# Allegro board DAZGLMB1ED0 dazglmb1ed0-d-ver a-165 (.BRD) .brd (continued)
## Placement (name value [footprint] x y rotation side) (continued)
C94914  10u/6.3V_4  [C0402_2]  236.34 74.79 0 bottom
C94915  10u/6.3V_4  [C0402_2]  269.72 61.94 0 bottom
C94916  10u/6.3V_4  [C0402_2]  227.34 74.95 270 bottom
C94918  10u/6.3V_4  [C0402_2]  221.76 66.49 180 bottom
C94919  0.022u/50V_4  [C0402]  239.35 69.61 0 bottom
C94921  *10u/6.3V_4  [C0402_2]  45.61 49.88 90 top
C94922  10u/6.3V_4  [C0402_2]  24.4 30.22 180 top
C94923  0.1u/10V_2  [C0201]  24.68 29.1 0 top
C94924  100p/50V_4  [C0402]  21.36 33.11 270 bottom
C94925  2.2u/10V_6  [C0603]  24.25 35.6 270 top
C94926  2.2u/10V_4  [C0402]  25.42 27.14 180 top
C94927  10u/6.3V_4  [C0402_2]  27.27 25.19 270 top
C94928  0.1u/10V_2  [C0201]  27.33 26.84 0 top
C94929  2.2u/10V_6  [C0603]  25.72 35.65 270 top
C94930  10u/6.3V_4  [C0402_2]  25.8 26 180 top
C94931  10u/6.3V_4  [C0402_2]  25.27 34.94 0 bottom
C94932  0.1u/10V_2  [C0201]  26.56 34.84 270 bottom
C94933  10u/6.3V_4  [C0402_2]  27.86 34.76 180 bottom
C94934  0.1u/10V_2  [C0201]  29.05 25.62 90 top
C94937  10u/6.3V_4  [C0402_2]  29.74 34.48 90 bottom
C94938  10u/6.3V_4  [C0402_2]  34.08 24.78 0 top
C94939  0.1u/10V_2  [C0201]  30.25 24.73 0 top
C94940  10u/6.3V_4  [C0402_2]  30.53 28.46 90 bottom
C94942  100p/50V_4  [C0402]  16.4 16.73 270 top
C94943  100p/50V_4  [C0402]  16.2 9.74 90 top
C94945  10u/6.3V_4  [C0402_2]  29.1 24.6 270 bottom
C94946  0.1u/10V_2  [C0201]  33.83 27.52 180 top
C94947  *22p/50V_4  [C0402]  32.35 33.7 90 bottom
C94951  *1000p/50V_4  [C0402]  15.67 31.56 90 bottom
C94952  100p/50V_4  [C0402]  20.98 23.66 270 top
C94953  100p/50V_4  [C0402]  23.24 27.02 270 top
C94956  *0.1u/10V_2  [C0201]  21.74 14.85 315 top
C94958  1000p/50V_4  [C0402]  21.48 12.41 90 top
C94959  1000p/50V_4  [C0402]  22.63 12.41 90 top
C94960  1000p/50V_4  [C0402]  23.77 12.41 90 top
C94961  1000p/50V_4  [C0402]  24.91 12.41 90 top
C94962  0.1u/10V_2  [C0201]  20.47 31.08 90 top
C94963  10u/6.3V_4  [C0402_2]  22.63 31.84 90 top
C94964  0.1u/10V_2  [C0201]  22.88 36.24 180 top
C94965  10u/6.3V_4  [C0402_2]  22.68 34.74 270 top
C94966  *1u/6.3V_2  [C0201]  34.56 29.07 270 top
C94967  *10p/50V_4  [C0402]  36.85 33.75 180 top
C94968  10p/50V_4  [C0402]  36.88 35.09 180 top
C94969  0.1u/10V_2  [C0201]  347.75 71.34 0 bottom
C94970  1u/6.3V_2  [C0201]  347.75 70.58 180 bottom
C94971  1000p/50V_4  [C0402]  343.68 67.1 270 top
C94972  0.1u/10V_2  [C0201]  342.82 67.3 270 top
C94973  10u/6.3V_4  [C0402_2]  344.83 67.1 270 top
C94974  0.1u/10V_2  [C0201]  347.72 72.86 180 bottom
C94975  0.1u/10V_2  [C0201]  348.36 75.4 270 top
C94976  0.1u/10V_2  [C0201]  349.12 75.4 270 top
C94977  1u/6.3V_2  [C0201]  350.67 68.75 270 bottom
C94978  0.1u/10V_2  [C0201]  349.88 68.75 90 bottom
C94979  10u/6.3V_4  [C0402_2]  346.72 65.45 180 top
C94980  0.1u/10V_2  [C0201]  351.43 68.75 90 bottom
C94981  0.1u/10V_2  [C0201]  351.78 74.08 90 bottom
C94982  10u/6.3V_4  [C0402_2]  346.86 66.67 180 top
C94983  1u/6.3V_2  [C0201]  347.49 67.76 270 top
C94984  1u/6.3V_2  [C0201]  352.22 68.75 270 bottom
C94985  0.1u/10V_2  [C0201]  346.73 67.76 90 top
C94986  *1000p/50V_4  [C0402]  346.86 67.02 180 bottom
C94987  0.1u/10V_2  [C0201]  353.08 70.58 180 bottom
C94988  0.1u/10V_2  [C0201]  353.08 72.86 0 bottom
C94989  0.1u/10V_2  [C0201]  353.08 72.1 0 bottom
C94990  1u/6.3V_2  [C0201]  353.08 71.34 0 bottom
C94991  18p/50V_4  [C0402]  352.62 66.62 0 top
C94992  0.01u/50V_4  [C0402]  358.8 67.02 90 bottom
C94993  18p/50V_4  [C0402]  350.9 66.62 180 top
C95000  1000p/3KV_1808  [CC1808]  366.42 80.23 180 top
C95002  4.7u/6.3V_4  [C0402_2]  189.5 110.58 0 bottom
C95003  1u/6.3V_2  [C0201]  156.87 122.14 270 bottom
C95004  1u/6.3V_2  [C0201]  188.23 113.12 180 bottom
C95005  1u/6.3V_2  [C0201]  166.85 122.01 270 bottom
C95006  0.22u/6.3V_2  [C0201]  156.43 108.55 270 bottom
C95007  22u/6.3V_6  [C0603]  138.83 126.84 270 bottom
C95008  10u/6.3V_4  [C0402_2]  161.49 124.35 0 bottom
C95009  10u/6.3V_4  [C0402_2]  161.49 125.54 0 bottom
C95010  0.22u/6.3V_2  [C0201]  158.59 107.15 270 bottom
C95011  4.7u/6.3V_4  [C0402_2]  137.43 122.65 270 bottom
C95012  22u/6.3V_6  [C0603]  190.39 109.19 180 bottom
C95013  10u/6.3V_4  [C0402_2]  188.87 111.85 0 bottom
C95014  10u/6.3V_4  [C0402_2]  168.17 122.39 90 bottom
C95015  1u/6.3V_2  [C0201]  153.01 122.01 270 bottom
C95016  4.7u/6.3V_4  [C0402_2]  154.45 102.58 90 bottom
C95017  0.22u/6.3V_2  [C0201]  154.78 108.42 270 bottom
C95018  0.22u/6.3V_2  [C0201]  155.54 108.42 270 bottom
C95019  0.22u/6.3V_2  [C0201]  157.2 108.55 270 bottom
C95020  0.22u/6.3V_2  [C0201]  157.83 107.15 270 bottom
C95021  4.7u/6.3V_4  [C0402_2]  140.23 126.71 90 bottom
C95022  1u/6.3V_2  [C0201]  151.91 127.98 180 bottom
C95023  1u/6.3V_2  [C0201]  151.91 125.7 180 bottom
C95024  1u/6.3V_2  [C0201]  161.44 121.86 180 bottom
C95025  1u/6.3V_2  [C0201]  164.72 122.01 270 bottom
C95026  0.22u/6.3V_2  [C0201]  159.1 106.14 90 bottom
C95027  0.22u/6.3V_2  [C0201]  159.86 106.14 90 bottom
C95028  0.22u/6.3V_2  [C0201]  160.5 109.44 90 bottom
C95029  0.22u/6.3V_2  [C0201]  161.26 109.44 90 bottom
C95030  0.22u/6.3V_2  [C0201]  161.39 107.79 90 bottom
C95031  0.22u/6.3V_2  [C0201]  162.15 107.79 90 bottom
C95032  0.22u/6.3V_2  [C0201]  162.91 108.04 90 bottom
C95033  0.1u/10V_2  [C0201]  163.37 122.95 90 bottom
C95034  0.22u/6.3V_2  [C0201]  163.67 108.04 90 bottom
C95035  0.22u/6.3V_2  [C0201]  164.18 109.95 90 bottom
C95036  0.22u/6.3V_2  [C0201]  164.94 109.95 90 bottom
C95037  0.22u/6.3V_2  [C0201]  164.94 108.17 90 bottom
C95038  0.22u/6.3V_2  [C0201]  165.7 108.17 90 bottom
C95039  0.22u/6.3V_2  [C0201]  166.09 107.15 90 bottom
C95040  0.22u/6.3V_2  [C0201]  166.85 107.15 90 bottom
C95041  0.22u/6.3V_2  [C0201]  167.13 108.93 90 bottom
C95042  0.22u/6.3V_2  [C0201]  167.89 108.93 90 bottom
C95043  0.22u/6.3V_2  [C0201]  168.24 107.53 90 bottom
C95044  0.22u/6.3V_2  [C0201]  169.01 107.53 90 bottom
C95045  0.22u/6.3V_2  [C0201]  169.74 107.53 90 bottom
C95046  0.22u/6.3V_2  [C0201]  170.5 107.53 90 bottom
C95047  0.1u/10V_2  [C0201]  170.91 132.2 180 bottom
C95048  22u/6.3V_6  [C0603]  166.64 102.71 0 top
C95049  0.22u/6.3V_2  [C0201]  170.53 109.31 90 bottom
C95050  0.22u/6.3V_2  [C0201]  171.29 109.31 90 bottom
C95051  0.22u/6.3V_2  [C0201]  171.67 107.53 90 bottom
C95052  0.22u/6.3V_2  [C0201]  172.44 107.53 90 bottom
C95053  0.1u/10V_2  [C0201]  162.55 141.22 90 bottom
C95054  0.1u/10V_2  [C0201]  170.94 127.35 0 bottom
C95055  0.22u/6.3V_2  [C0201]  172.82 106.14 90 bottom
C95056  0.22u/6.3V_2  [C0201]  173.58 106.14 90 bottom
C95057  0.1u/10V_2  [C0201]  134.77 115.03 180 top
C95058  0.1u/10V_2  [C0201]  153.82 141.19 90 bottom
C95059  0.1u/10V_2  [C0201]  154.58 141.19 270 bottom
C95060  0.1u/10V_2  [C0201]  151.3 137.05 0 bottom
C95065  0.1u/10V_2  [C0201]  151.59 122.01 270 bottom
C95066  4.7u/6.3V_4  [C0402_2]  154.45 100.42 90 bottom
C95067  4.7u/6.3V_4  [C0402_2]  155.85 102.58 270 bottom
C95068  0.1u/10V_2  [C0201]  154.93 122.14 270 bottom
C95069  1u/6.3V_2  [C0201]  165.43 122.01 90 bottom
C95070  0.1u/10V_2  [C0201]  159.66 121.96 270 bottom
C95071  4.7u/6.3V_4  [C0402_2]  158.26 122.52 270 bottom
C95072  4.7u/6.3V_4  [C0402_2]  157.25 100.42 90 bottom
C95073  1u/6.3V_2  [C0201]  155.64 122.17 90 bottom
C95074  4.7u/6.3V_4  [C0402_2]  155.85 100.42 90 bottom
C95075  4.7u/6.3V_4  [C0402_2]  153.97 122.39 270 bottom
C95076  0.1u/10V_2  [C0201]  169.64 122.01 270 bottom
C95077  1u/6.3V_2  [C0201]  166.14 122.01 90 bottom
C95078  0.1u/10V_2  [C0201]  124.99 104.61 180 top
C95079  *220p/50V_4  [C0402]  133.55 117.44 270 top
C95080  *220p/50V_4  [C0402]  130.2 116.17 90 bottom
C95081  *220p/50V_4  [C0402]  142.44 101.41 180 top
C95082  1u/6.3V_2  [C0201]  170.94 130.45 0 bottom
C95083  1u/6.3V_2  [C0201]  170.94 131.46 0 bottom
C95084  1u/6.3V_2  [C0201]  156.1 141.19 90 bottom
C95085  10u/6.3V_4  [C0402_2]  118.64 154.4 180 bottom
C95086  1u/6.3V_2  [C0201]  170.94 134.18 0 bottom
C95087  10u/6.3V_4  [C0402_2]  203.22 145.04 180 bottom
C95088  1u/6.3V_2  [C0201]  151.4 130.01 180 bottom
C95089  10u/6.3V_4  [C0402_2]  201.49 145.04 0 bottom
C95090  1u/6.3V_2  [C0201]  171.22 139.67 0 bottom
C95091  10u/6.3V_4  [C0402_2]  163.88 140.89 90 bottom
C95092  1u/6.3V_2  [C0201]  155.34 141.19 90 bottom
C95093  10u/6.3V_4  [C0402_2]  168.55 156.56 270 bottom
C95094  1u/6.3V_2  [C0201]  170.94 134.94 0 bottom
C95095  10u/6.3V_4  [C0402_2]  152.85 141.57 90 bottom
C95096  1u/6.3V_2  [C0201]  170.94 135.75 0 bottom
C95097  10u/6.3V_4  [C0402_2]  181 163.16 0 bottom
C95098  1u/6.3V_2  [C0201]  165.02 141.24 90 bottom
C95099  *10u/6.3V_4  [C0402_2]  170.56 126.38 0 bottom
C95100  1u/6.3V_2  [C0201]  151.23 135.47 180 bottom
C95101  47u/6.3V_6  [C0603]  151.33 140.48 90 bottom
C95102  1u/6.3V_2  [C0201]  151.66 133.34 180 bottom
C95103  22u/6.3V_6  [C0603]  184.14 146.19 180 bottom
C95104  1u/6.3V_2  [C0201]  170.96 133.47 0 bottom
C95105  22u/6.3V_6  [C0603]  118.26 171.16 0 top
C95106  1u/6.3V_2  [C0201]  170.94 128.08 0 bottom
C95107  22u/6.3V_6  [C0603]  182.75 132.78 90 bottom
C95108  1u/6.3V_2  [C0201]  151.66 134.05 180 bottom
C95109  22u/6.3V_6  [C0603]  139.59 138.52 180 bottom
C95110  1u/6.3V_2  [C0201]  165.73 141.24 90 bottom
C95111  22u/6.3V_6  [C0603]  174.77 156.68 270 bottom
C95112  1u/6.3V_2  [C0201]  151.28 136.26 180 bottom
C95113  22u/6.3V_6  [C0603]  173.12 156.68 270 bottom
C95114  1u/6.3V_2  [C0201]  156.87 141.19 90 bottom
C95115  22u/6.3V_6  [C0603]  118.26 169.64 0 top
C95116  1u/6.3V_2  [C0201]  151.3 138.57 180 bottom
C95117  22u/6.3V_6  [C0603]  138.73 148.58 180 bottom
C95118  1u/6.3V_2  [C0201]  151.3 137.86 180 bottom
C95119  *47u/6.3V_6  [C0603]  139.59 136.11 180 bottom
C95120  1u/6.3V_2  [C0201]  170.94 136.52 0 bottom
C95121  1u/6.3V_2  [C0201]  157.63 141.19 90 bottom
C95122  1u/6.3V_2  [C0201]  151.4 130.78 180 bottom
C95123  1u/6.3V_2  [C0201]  170.94 128.82 0 bottom
C95124  10u/6.3V_4  [C0402_2]  158.87 141.55 90 bottom
C95125  10u/6.3V_4  [C0402_2]  168.22 141.27 0 bottom
C95126  10u/6.3V_4  [C0402_2]  170.07 141.22 0 bottom
C95127  10u/6.3V_4  [C0402_2]  169.95 156.56 270 bottom
C95128  10u/6.3V_4  [C0402_2]  202.59 126.46 0 bottom
C95129  *47u/6.3V_6  [C0603]  138.73 145.66 180 bottom
C95130  *47u/6.3V_6  [C0603]  184.14 144.54 180 bottom
C95131  0.1u/10V_2  [C0201]  150.72 121.89 180 bottom
C95132  0.1u/10V_2  [C0201]  150.72 122.6 180 bottom
C95133  4.7u/6.3V_4  [C0402_2]  103.53 66.77 180 bottom
C95134  1u/6.3V_2  [C0201]  134.89 122.27 90 bottom
C95135  1u/6.3V_2  [C0201]  150.62 127.91 270 bottom
C95136  1u/6.3V_2  [C0201]  161.44 123.38 180 bottom
C95137  1u/6.3V_2  [C0201]  161.44 122.62 180 bottom
C95138  4.7u/6.3V_4  [C0402_2]  151.86 124.43 90 bottom
C95139  4.7u/6.3V_4  [C0402_2]  139.97 122.65 90 bottom
C95140  4.7u/6.3V_4  [C0402_2]  138.7 122.65 90 bottom
C95141  0.1u/10V_2  [C0201]  150.77 125.44 180 bottom
C95142  0.1u/10V_2  [C0201]  150.77 124.02 180 bottom
C95143  0.1u/10V_2  [C0201]  150.77 126.15 180 bottom
C95144  0.1u/10V_2  [C0201]  151.91 127.22 180 bottom
C95145  0.1u/10V_2  [C0201]  150.77 123.31 180 bottom
C95146  0.1u/10V_2  [C0201]  150.77 124.73 180 bottom
C95147  0.1u/10V_2  [C0201]  151.91 126.46 180 bottom
C95148  0.1u/10V_2  [C0201]  125.32 120.39 0 top
C95149  *0.1u/10V_2  [C0201]  113.81 120.11 0 bottom
C95150  *60@0.22u/6.3V_2  [C0201]  121.31 120.11 0 bottom
C95151  0.1u/10V_2  [C0201]  152.3 122.01 270 bottom
C95152  0.1u/10V_2  [C0201]  152.29 111.98 0 bottom
C95153  4.7u/6.3V_4  [C0402_2]  151.53 110.46 0 bottom
C95154  0.1u/10V_2  [C0201]  153.82 112.74 0 bottom
C95155  0.1u/10V_2  [C0201]  170.94 137.25 180 bottom
C95156  0.1u/10V_2  [C0201]  151.28 131.92 270 bottom
C95157  22u/6.3V_6  [C0603]  153.06 107.79 0 bottom
C95158  *0.1u/10V_2  [C0201]  121.81 114.27 0 bottom
C95159  10p/50V_4  [C0402]  148.1 107.79 180 top
C95160  10p/50V_4  [C0402]  146.32 107.79 0 top
C95161  22u/6.3V_6  [C0603]  178.68 107.56 0 top
C95162  22u/6.3V_6  [C0603]  186.13 113.63 270 top
C95163  47u/6.3V_6  [C0603]  157.02 132.07 270 bottom
C95164  47u/6.3V_6  [C0603]  155.6 132.05 270 bottom
C95165  47u/6.3V_6  [C0603]  165.42 128.54 270 bottom
C95166  47u/6.3V_6  [C0603]  164 128.54 270 bottom
C95167  47u/6.3V_6  [C0603]  164.49 131.36 90 bottom
C95168  *22u/6.3V_6  [C0603]  182.39 122.14 270 bottom
C95169  1u/6.3V_2  [C0201]  158.29 129.84 270 bottom
C95170  1u/6.3V_2  [C0201]  158.31 138.22 270 bottom
C95171  10u/6.3V_4  [C0402_2]  169.44 124.83 270 bottom
C95172  1u/6.3V_2  [C0201]  156.03 140.33 180 bottom
C95173  1u/6.3V_2  [C0201]  162.96 131.49 180 bottom
C95174  47u/6.3V_6  [C0603]  161.13 133.16 180 bottom
C95175  47u/6.3V_6  [C0603]  156.28 134.46 180 bottom
C95176  10u/6.3V_4  [C0402_2]  169.46 134.43 90 bottom
C95177  1u/6.3V_2  [C0201]  158.31 125.06 90 bottom
C95178  10u/6.3V_4  [C0402_2]  168.14 124.76 270 bottom
C95179  10u/6.3V_4  [C0402_2]  166.69 135.25 90 bottom
C95180  1u/6.3V_2  [C0201]  166.75 124.98 90 bottom
C95181  10u/6.3V_4  [C0402_2]  160.37 141.29 0 bottom
C95182  1u/6.3V_2  [C0201]  154.1 131.56 270 bottom
C95183  10u/6.3V_4  [C0402_2]  165.27 139.51 90 bottom
C95184  1u/6.3V_2  [C0201]  159.66 122.95 90 bottom
C95185  10u/6.3V_4  [C0402_2]  169.57 128.95 90 bottom
C95186  1u/6.3V_2  [C0201]  154.12 136.16 90 bottom
C95187  1u/6.3V_2  [C0201]  154.12 128.77 90 bottom
C95188  10u/6.3V_4  [C0402_2]  165.27 135.25 90 bottom
C95189  1u/6.3V_2  [C0201]  168.09 138.19 270 bottom
C95190  1u/6.3V_2  [C0201]  168.12 136.62 270 bottom
C95191  10u/6.3V_4  [C0402_2]  171.5 124.25 270 bottom
C95192  1u/6.3V_2  [C0201]  156.92 136.26 270 bottom
C95193  1u/6.3V_2  [C0201]  169.51 123.46 90 bottom
C95194  10u/6.3V_4  [C0402_2]  166.69 140.38 270 bottom
C95195  1u/6.3V_2  [C0201]  156.89 139.54 270 bottom
C95196  1u/6.3V_2  [C0201]  154.1 134.48 90 bottom
C95197  10u/6.3V_4  [C0402_2]  171.24 122.17 0 bottom
C95198  1u/6.3V_2  [C0201]  168.04 128.16 270 bottom
C95199  1u/6.3V_2  [C0201]  169.54 131.33 90 bottom
C95200  1u/6.3V_2  [C0201]  153.08 131.39 270 bottom
C95201  1u/6.3V_2  [C0201]  162.35 126.58 180 bottom
C95202  47u/6.3V_6  [C0603]  161.11 135.98 0 bottom
C95203  1u/6.3V_2  [C0201]  154.15 138.85 90 bottom
C95204  1u/6.3V_2  [C0201]  169.54 137.23 90 bottom
C95205  22u/6.3V_6  [C0603]  183.92 122.14 270 bottom
C95206  1u/6.3V_2  [C0201]  154.12 126.76 270 bottom
C95207  1u/6.3V_2  [C0201]  153.92 123.64 180 bottom
C95208  22u/6.3V_6  [C0603]  178.71 105.88 0 top
C95209  1u/6.3V_2  [C0201]  158.31 124.04 270 bottom
C95210  1u/6.3V_2  [C0201]  168.04 139.54 270 bottom
C95211  47u/6.3V_6  [C0603]  161.11 127.96 180 bottom
C95212  1u/6.3V_2  [C0201]  158.9 136.52 270 bottom
C95213  1u/6.3V_2  [C0201]  152.04 129 90 bottom
C95214  1u/6.3V_2  [C0201]  152.14 135.81 90 bottom
C95215  1u/6.3V_2  [C0201]  169.54 136.24 270 bottom
C95216  1u/6.3V_2  [C0201]  158.29 128.85 90 bottom
C95217  1u/6.3V_2  [C0201]  154.17 140.12 90 bottom
C95218  1u/6.3V_2  [C0201]  163.88 135.27 270 bottom
C95219  1u/6.3V_2  [C0201]  156.89 128.85 90 bottom
C95220  1u/6.3V_2  [C0201]  155.52 126.79 270 bottom
C95221  1u/6.3V_2  [C0201]  154.1 125.01 90 bottom
C95222  10u/6.3V_4  [C0402_2]  160.95 131.66 180 bottom
C95223  10u/6.3V_4  [C0402_2]  168.07 134.54 270 bottom
C95224  1u/6.3V_2  [C0201]  156.89 129.84 270 bottom
C95225  10u/6.3V_4  [C0402_2]  168.14 131 270 bottom
C95226  47u/6.3V_6  [C0603]  165.91 131.36 90 bottom
C95227  1u/6.3V_2  [C0201]  165.32 133.6 270 bottom
C95228  10u/6.3V_4  [C0402_2]  154.15 132.99 270 bottom
C95229  47u/6.3V_6  [C0603]  170.23 138.45 180 bottom
C95230  1u/6.3V_2  [C0201]  163.49 126.46 0 bottom
C95231  47u/6.3V_6  [C0603]  161.11 137.41 0 bottom
C95232  1u/6.3V_2  [C0201]  160.68 126.51 180 bottom
C95233  1u/6.3V_2  [C0201]  166.64 133.6 270 bottom
C95234  1u/6.3V_2  [C0201]  156.84 126.81 270 bottom
C95235  47u/6.3V_6  [C0603]  161.11 139.84 180 bottom
C95236  1u/6.3V_2  [C0201]  163.93 137.96 270 bottom
C95237  47u/6.3V_6  [C0603]  161.11 129.38 0 bottom
C95238  330u/2V_7343H1.9  [CC7343]  197.25 101.13 0 top
C95239  1u/6.3V_2  [C0201]  169.9 132.88 0 bottom
C95240  1u/6.3V_2  [C0201]  166.67 137.86 270 bottom
C95241  1u/6.3V_2  [C0201]  154.12 130.52 90 bottom
C95242  330u/2V_7343H1.9  [CC7343]  196.73 96.37 0 top
C95243  1u/6.3V_2  [C0201]  168.07 129.58 270 bottom
C95244  1u/6.3V_2  [C0201]  160.27 124.68 90 bottom
C95245  1u/6.3V_2  [C0201]  163.9 133.57 270 bottom
C95246  1u/6.3V_2  [C0201]  155.54 128.85 90 bottom
C95247  1u/6.3V_2  [C0201]  156.84 138.01 270 bottom
C95248  1u/6.3V_2  [C0201]  165.25 126.1 90 bottom
C95249  1u/6.3V_2  [C0201]  155.57 125.09 90 bottom
C95250  1u/6.3V_2  [C0201]  158.41 140.12 90 bottom
C95251  1u/6.3V_2  [C0201]  152.01 131.92 270 bottom
C95252  1u/6.3V_2  [C0201]  155.54 129.84 270 bottom
C95253  1u/6.3V_2  [C0201]  165.27 137.96 270 bottom
C95254  1u/6.3V_2  [C0201]  156.89 124.02 270 bottom
C95255  1u/6.3V_2  [C0201]  156.89 125.09 90 bottom
C95256  1u/6.3V_2  [C0201]  158.29 126.79 270 bottom
C95257  1u/6.3V_2  [C0201]  168.04 127.17 90 bottom
C95258  1u/6.3V_2  [C0201]  163.9 139.46 270 bottom
C95259  1u/6.3V_2  [C0201]  155.57 124.07 270 bottom
C95260  1u/6.3V_2  [C0201]  168.09 133.16 90 bottom
C95261  1u/6.3V_2  [C0201]  155.62 136.29 270 bottom
C95496  1u/6.3V_2  [C0201]  23.18 63.42 270 top
C95498  0.1u/10V_2  [C0201]  16.96 45.61 180 bottom
C95499  22u/6.3V_4  [C0402]  17.04 44.52 0 bottom
C95500  22u/6.3V_4  [C0402_2]  17.04 43.25 180 bottom
C95501  0.1u/10V_2  [C0201]  16.89 40.4 90 bottom
C95502  22u/6.3V_4  [C0402]  18.44 64.1 270 top
C95503  0.1u/10V_2  [C0201]  17.55 64.1 90 top
C95504  22u/6.3V_4  [C0402_2]  17.67 66.51 270 top
C95505  100u/6.3V_12  [C1206]  20.72 66.64 0 top
C95506  0.1u/10V_2  [C0201]  23.13 43.27 270 top
C95507  0.1u/10V_2  [C0201]  23.9 43.27 270 top
C95508  10u/6.3V_4  [C0402_2]  32.41 50.26 180 bottom
C95509  0.1u/10V_2  [C0201]  24.73 47.26 270 bottom
C95510  0.1u/10V_2  [C0201]  23.9 47.26 270 bottom
C95511  0.1u/10V_2  [C0201]  32.02 46.07 180 top
C95512  0.1u/10V_2  [C0201]  32.02 45.3 180 top
C95513  0.1u/10V_2  [C0201]  32.02 47.72 180 top
C95514  0.1u/10V_2  [C0201]  32.02 46.96 180 top
C95515  0.1u/10V_2  [C0201]  32.02 49.37 180 top
C95516  0.1u/10V_2  [C0201]  16.78 48.73 90 bottom
C95517  0.1u/10V_2  [C0201]  32.02 48.61 180 top
C95518  0.1u/10V_2  [C0201]  32.02 51.91 180 top
C95519  0.1u/10V_2  [C0201]  32.02 51.15 180 top
C95520  0.1u/10V_2  [C0201]  23.64 51.4 180 top
C95521  0.1u/10V_2  [C0201]  23.64 50.51 180 top
C95522  1u/6.3V_2  [C0201]  25.42 88.05 180 top
C95524  470p/50V_4  [C0402]  25.67 82.52 270 bottom
C95525  0.1u/10V_2  [C0201]  26.18 85.06 180 bottom
C95526  10u/6.3V_4  [C0402_2]  26.94 82.52 90 bottom
C95527  100u/6.3V_12  [C1206]  26.31 79.85 270 top
C95528  22u/6.3V_4  [C0402_2]  369.44 53.31 90 top
C95529  0.1u/10V_2  [C0201]  368.45 55.34 270 top
C95530  22u/6.3V_4  [C0402_2]  367.08 55.23 0 top
C95531  47u/6.3V_8  [C0805]  367.56 51.3 90 top
C95532  0.1u/10V_2  [C0201]  26.18 84.29 180 bottom
C95533  0.1u/10V_2  [C0201]  369.34 55.34 270 top
C95534  1u/6.3V_2  [C0201]  360.93 54.07 90 top
C95538  0.1u/10V_2  [C0201]  364.23 57.01 0 top
C95539  0.1u/10V_2  [C0201]  364.23 57.75 0 top
C95540  10u/6.3V_4  [C0402_2]  49.8 73.75 0 top
C95541  0.1u/10V_2  [C0201]  52.98 73.37 0 bottom
C95542  0.1u/10V_2  [C0201]  51.07 72.61 270 top
C95543  0.1u/10V_2  [C0201]  52.98 74.26 0 bottom
C95544  0.1u/10V_2  [C0201]  50.31 72.61 270 top
C95545  10u/6.3V_4  [C0402_2]  49.93 56.86 270 top
C95546  0.1u/10V_2  [C0201]  51.07 56.73 270 top
C95547  0.1u/10V_2  [C0201]  50.19 56.73 270 bottom
C95548  0.1u/10V_2  [C0201]  51.07 56.73 270 bottom
C95553  10u/6.3V_4  [C0402_2]  60.14 26.33 180 bottom
C95554  0.1u/10V_2  [C0201]  60.12 27.4 0 bottom
C95555  0.1u/10V_2  [C0201]  60.98 23.33 270 top
C95556  0.1u/10V_2  [C0201]  75.84 21.05 0 bottom
C95557  10u/6.3V_4  [C0402_2]  74.01 22.14 0 top
C95558  0.1u/10V_2  [C0201]  60.22 23.33 270 top
C95559  0.1u/10V_2  [C0201]  75.84 20.16 0 bottom
C95560  0.1u/10V_2  [C0201]  56.79 20.41 180 bottom
C95561  0.1u/10V_2  [C0201]  56.79 19.52 180 bottom
C95562  0.1u/10V_2  [C0201]  63.77 23.33 270 top
C95563  0.1u/10V_2  [C0201]  64.54 23.33 270 top
C95564  0.1u/10V_2  [C0201]  67.3 23.33 270 top
C95565  0.1u/10V_2  [C0201]  68.04 23.33 270 top
C95566  SSD@0.1u/10V_2  [C0201]  69.84 23.99 0 top
C95567  SSD@0.1u/10V_2  [C0201]  69.84 24.76 0 top
C95573  10u/6.3V_4  [C0402_2]  57.07 37.79 180 bottom
C95574  1u/6.3V_2  [C0201]  64.05 35.32 0 bottom
C95575  1u/6.3V_2  [C0201]  57.55 36.67 90 bottom
C95576  0.1u/10V_2  [C0201]  57.83 32.94 180 bottom
C95577  0.1u/10V_2  [C0201]  61.95 30.83 180 bottom
C95578  0.22u/6.3V_2  [C0201]  65.61 37.94 0 top
C95580  0.22u/6.3V_2  [C0201]  63.44 39.29 90 top
C95581  0.22u/6.3V_2  [C0201]  65.61 37.17 0 top
C95583  0.22u/6.3V_2  [C0201]  62.68 39.29 90 top
C95591  1u/6.3V_2  [C0201]  67.84 44.67 90 bottom
C95593  10u/6.3V_4  [C0402_2]  67.28 45.79 180 bottom
C95594  1u/6.3V_2  [C0201]  74.42 44.29 0 bottom
C95595  0.1u/10V_2  [C0201]  71.8 39.51 180 bottom
C95596  0.1u/10V_2  [C0201]  68.04 41.37 180 bottom
C95623  10u/6.3V_4  [C0402_2]  47.57 30.47 270 top
C95624  0.1u/10V_2  [C0201]  46.53 30.42 90 top
C95625  10u/6.3V_4  [C0402_2]  28.72 21.43 90 bottom
C95626  0.1u/10V_2  [C0201]  32.28 22.7 270 top
C95627  0.1u/10V_2  [C0201]  31.39 19.52 180 bottom
C95628  0.1u/10V_2  [C0201]  33.04 22.7 270 top
C95629  0.1u/10V_2  [C0201]  49.35 19.78 0 bottom
C95630  0.1u/10V_2  [C0201]  49.35 20.67 0 bottom
C95631  0.1u/10V_2  [C0201]  31.39 20.41 180 bottom
C95632  0.1u/10V_2  [C0201]  35.83 22.83 270 top
C95633  0.1u/10V_2  [C0201]  36.6 22.83 270 top
C95634  0.1u/10V_2  [C0201]  39.39 22.7 270 top
C95635  0.1u/10V_2  [C0201]  40.15 22.7 270 top
C95636  0.1u/10V_2  [C0201]  42.88 22.7 270 top
C95637  0.1u/10V_2  [C0201]  43.6 22.7 270 top
C95674  47u/6.3V_6  [C0603]  193.05 137.93 180 bottom
C95675  22u/6.3V_6  [C0603]  208.16 143.39 270 bottom
C95676  22u/6.3V_6  [C0603]  205.5 145.17 180 bottom
C95677  22u/6.3V_6  [C0603]  205.25 132.16 180 bottom
C95678  22u/6.3V_6  [C0603]  194.77 132.11 0 bottom
C95679  1u/6.3V_2  [C0201]  197.33 137.66 180 bottom
C95680  1u/6.3V_2  [C0201]  198.39 140.17 0 bottom
C95681  1u/6.3V_2  [C0201]  194.78 139.63 180 bottom
C95682  1u/6.3V_2  [C0201]  195.38 137.68 0 bottom
C95683  1u/6.3V_2  [C0201]  200.67 140.16 270 bottom
C95684  1u/6.3V_2  [C0201]  203.72 138.31 0 bottom
C95685  1u/6.3V_2  [C0201]  201.86 138.32 180 bottom
C95686  1u/6.3V_2  [C0201]  195.46 154.31 180 bottom
C95687  10u/6.3V_4  [C0402_2]  203.47 131.16 180 top
C95688  10u/6.3V_4  [C0402_2]  196.62 131.16 180 top
C95689  *22u/6.3V_6  [C0603]  191.08 133.94 90 bottom
C95690  *22u/6.3V_6  [C0603]  191.16 143.81 270 bottom
C95691  820p/50V_4  [C0402]  201.57 130.9 180 top
C95692  1u/6.3V_2  [C0201]  192.67 141.49 90 bottom
C95693  1u/6.3V_2  [C0201]  207.54 140.68 90 bottom
C95694  22u/6.3V_6  [C0603]  205.24 126.47 180 bottom
C95695  22u/6.3V_6  [C0603]  206.27 112.11 0 top
C95696  22u/6.3V_6  [C0603]  197.37 113.49 0 bottom
C95697  22u/6.3V_6  [C0603]  207.79 121.12 270 bottom
C95698  47u/6.3V_6  [C0603]  191.91 122.13 270 bottom
C95699  1u/6.3V_2  [C0201]  197 119.22 180 bottom
C95700  1u/6.3V_2  [C0201]  204.48 120.46 180 bottom
C95701  1u/6.3V_2  [C0201]  201.94 120.48 180 bottom
C95702  1u/6.3V_2  [C0201]  195.34 119.21 180 bottom
C95703  1u/6.3V_2  [C0201]  194.95 113.75 0 bottom
C95704  1u/6.3V_2  [C0201]  197.24 121.11 180 bottom
C95705  1u/6.3V_2  [C0201]  200.42 118.45 90 bottom
C95706  1u/6.3V_2  [C0201]  194.73 121.18 180 bottom
C95707  10u/6.3V_4  [C0402_2]  201.82 113.5 0 bottom
C95708  10u/6.3V_4  [C0402_2]  183.28 165.19 90 bottom
C95709  *22u/6.3V_6  [C0603]  194.45 126.7 0 bottom
C95710  *22u/6.3V_6  [C0603]  197.11 126.7 180 bottom
C95711  820p/50V_4  [C0402]  201.57 127.47 180 top
C95712  1u/6.3V_2  [C0201]  207.08 117.59 180 bottom
C95713  1u/6.3V_2  [C0201]  192.46 115.53 180 bottom
C95714  22u/6.3V_6  [C0603]  180.67 179.28 180 bottom
C95715  47u/6.3V_6  [C0603]  171.4 163.28 90 bottom
C95716  22u/6.3V_6  [C0603]  177.88 163.28 270 bottom
C95717  22u/6.3V_6  [C0603]  182.83 174.71 90 bottom
C95718  22u/6.3V_6  [C0603]  177.37 179.28 0 bottom
C95719  1u/6.3V_2  [C0201]  175.59 165.69 270 bottom
C95720  1u/6.3V_2  [C0201]  176.86 172.8 270 bottom
C95721  1u/6.3V_2  [C0201]  177.63 165.69 270 bottom
C95722  1u/6.3V_2  [C0201]  175.85 174.2 270 bottom
C95723  1u/6.3V_2  [C0201]  177.63 168.36 270 bottom
C95724  1u/6.3V_2  [C0201]  169.99 172.89 90 bottom
C95725  1u/6.3V_2  [C0201]  176.93 176.75 270 bottom
C95726  1u/6.3V_2  [C0201]  174.96 169.63 90 bottom
C95727  10u/6.3V_4  [C0402_2]  169.52 166.75 270 bottom
C95728  10u/6.3V_4  [C0402_2]  169.99 174.62 270 bottom
C95729  *22u/6.3V_6  [C0603]  182.82 177.38 90 bottom
C95730  *22u/6.3V_6  [C0603]  169.95 176.88 270 bottom
C95731  820p/50V_4  [C0402]  183.66 171.41 270 bottom
C95732  1u/6.3V_2  [C0201]  173.18 179.15 0 bottom
C95733  1u/6.3V_2  [C0201]  173.18 162.77 0 bottom
C95734  22u/6.3V_6  [C0603]  195.85 162.14 180 bottom
C95735  47u/6.3V_6  [C0603]  191.21 150.63 90 bottom
C95736  22u/6.3V_6  [C0603]  197.51 148.62 0 bottom
C95737  22u/6.3V_6  [C0603]  192.97 148.45 0 bottom
C95738  22u/6.3V_6  [C0603]  208.35 159.16 270 bottom
C95739  1u/6.3V_2  [C0201]  197.88 154.31 180 bottom
C95740  1u/6.3V_2  [C0201]  205.88 119.26 180 bottom
C95741  1u/6.3V_2  [C0201]  197.4 156.11 180 bottom
C95742  1u/6.3V_2  [C0201]  195.32 156.12 0 bottom
C95743  1u/6.3V_2  [C0201]  202.52 155.49 180 bottom
C95744  1u/6.3V_2  [C0201]  201.39 154.44 180 bottom
C95745  1u/6.3V_2  [C0201]  202.38 153.13 0 bottom
C95746  1u/6.3V_2  [C0201]  204.5 155.5 180 bottom
C95747  10u/6.3V_4  [C0402_2]  195.25 148.81 0 bottom
C95748  10u/6.3V_4  [C0402_2]  193.57 162.02 180 bottom
C95749  *22u/6.3V_6  [C0603]  202.57 161.55 0 bottom
C95750  *22u/6.3V_6  [C0603]  205.37 161.55 180 bottom
C95751  820p/50V_4  [C0402]  200.35 161.89 270 bottom
C95752  1u/6.3V_2  [C0201]  192.92 151.88 270 bottom
C95753  1u/6.3V_2  [C0201]  207.78 152.66 180 bottom
C95754  22u/6.3V_6  [C0603]  126.04 164.63 90 bottom
C95755  22u/6.3V_6  [C0603]  126.26 173.7 270 bottom
C95756  22u/6.3V_6  [C0603]  139.98 164.8 270 bottom
C95757  47u/6.3V_6  [C0603]  128.16 162.68 180 bottom
C95758  22u/6.3V_6  [C0603]  137.19 179.15 180 bottom
C95759  1u/6.3V_2  [C0201]  131.35 171.53 0 bottom
C95760  1u/6.3V_2  [C0201]  133.5 175.61 270 bottom
C95761  1u/6.3V_2  [C0201]  134.2 165.67 270 bottom
C95762  1u/6.3V_2  [C0201]  132.27 176.78 270 bottom
C95763  1u/6.3V_2  [C0201]  133.61 172.68 270 bottom
C95764  1u/6.3V_2  [C0201]  132.36 165.82 270 bottom
C95765  1u/6.3V_2  [C0201]  134.23 168.3 270 bottom
C95766  1u/6.3V_2  [C0201]  131.55 169.56 90 bottom
C95767  10u/6.3V_4  [C0402_2]  126.13 166.97 90 bottom
C95768  10u/6.3V_4  [C0402_2]  139.21 177 90 bottom
C95769  *22u/6.3V_6  [C0603]  139.09 174.71 90 bottom
C95770  *22u/6.3V_6  [C0603]  134.52 179.15 0 bottom
C95771  820p/50V_4  [C0402]  142.26 172.94 0 bottom
C95772  1u/6.3V_2  [C0201]  128.93 178.91 0 bottom
C95773  1u/6.3V_2  [C0201]  131.22 163.91 180 bottom
C95774  47u/6.3V_6  [C0603]  145.18 165.32 270 bottom
C95775  22u/6.3V_6  [C0603]  157.56 173.31 270 bottom
C95776  22u/6.3V_6  [C0603]  144.38 176.49 90 bottom
C95777  22u/6.3V_6  [C0603]  144.38 173.82 90 bottom
C95778  22u/6.3V_6  [C0603]  155.47 178.91 180 bottom
C95779  1u/6.3V_2  [C0201]  150.57 175.85 270 bottom
C95780  1u/6.3V_2  [C0201]  150.57 174.07 270 bottom
C95781  1u/6.3V_2  [C0201]  149.81 167.61 90 bottom
C95782  1u/6.3V_2  [C0201]  151.84 168.23 90 bottom
C95783  1u/6.3V_2  [C0201]  151.72 174.2 270 bottom
C95784  1u/6.3V_2  [C0201]  151.84 170.01 90 bottom
C95785  1u/6.3V_2  [C0201]  151.72 165.69 270 bottom
C95786  1u/6.3V_2  [C0201]  149.82 165.72 270 bottom
C95787  10u/6.3V_4  [C0402_2]  157.37 168.75 90 bottom
C95788  10u/6.3V_4  [C0402_2]  145.18 167.73 270 bottom
C95789  *22u/6.3V_6  [C0603]  146.51 162.64 180 bottom
C95790  *22u/6.3V_6  [C0603]  146.76 179.03 180 bottom
C95791  820p/50V_4  [C0402]  136.58 170.62 0 bottom
C95792  1u/6.3V_2  [C0201]  154.51 162.64 0 bottom
C95793  1u/6.3V_2  [C0201]  153.23 177.84 0 bottom
C95794  47u/6.3V_6  [C0603]  129.17 122.29 180 bottom
C95795  47u/6.3V_6  [C0603]  116.9 122.69 0 bottom
C95796  22u/6.3V_6  [C0603]  118.8 135.52 180 bottom
C95797  22u/6.3V_6  [C0603]  131.06 130.87 270 bottom
C95798  47u/6.3V_6  [C0603]  131.05 133.68 270 bottom
C95799  1u/6.3V_2  [C0201]  117.35 129.63 180 bottom
C95800  1u/6.3V_2  [C0201]  121.66 128.1 90 bottom
C95801  1u/6.3V_2  [C0201]  121.31 129.63 180 bottom
C95802  1u/6.3V_2  [C0201]  118.79 128.3 0 bottom
C95803  1u/6.3V_2  [C0201]  127 130.24 180 bottom
C95804  1u/6.3V_2  [C0201]  127.66 128.28 0 bottom
C95805  1u/6.3V_2  [C0201]  125.04 130.22 0 bottom
C95806  1u/6.3V_2  [C0201]  123.82 127.85 180 bottom
C95807  10u/6.3V_4  [C0402_2]  116.31 135.43 180 bottom
C95808  10u/6.3V_4  [C0402_2]  126.94 122.52 0 bottom
C95809  *22u/6.3V_6  [C0603]  131.21 124.09 90 bottom
C95810  *22u/6.3V_6  [C0603]  129.64 135.8 180 bottom
C95811  820p/50V_4  [C0402]  121.77 135.55 270 bottom
C95812  1u/6.3V_2  [C0201]  115.34 125.44 90 bottom
C95813  1u/6.3V_2  [C0201]  130.84 126.5 90 bottom
C95814  22u/6.3V_6  [C0603]  127.51 141.11 0 bottom
C95815  22u/6.3V_6  [C0603]  125.73 154.57 0 bottom
C95816  22u/6.3V_6  [C0603]  116.97 140.39 0 top
C95817  22u/6.3V_6  [C0603]  119.76 140.34 180 top
C95818  47u/6.3V_6  [C0603]  128.78 147.07 180 bottom
C95819  1u/6.3V_2  [C0201]  123.82 148.6 180 bottom
C95820  1u/6.3V_2  [C0201]  148.56 156.3 270 bottom
C95821  1u/6.3V_2  [C0201]  128.8 149.32 0 bottom
C95822  1u/6.3V_2  [C0201]  117.87 147.45 0 bottom
C95823  1u/6.3V_2  [C0201]  121.31 147.41 180 bottom
C95824  1u/6.3V_2  [C0201]  120.85 148.43 0 bottom
C95825  1u/6.3V_2  [C0201]  126.74 146.82 180 bottom
C95826  1u/6.3V_2  [C0201]  124.84 146.82 0 bottom
C95827  10u/6.3V_4  [C0402_2]  128.16 154.52 0 bottom
C95828  10u/6.3V_4  [C0402_2]  127.76 142.63 180 bottom
C95829  *22u/6.3V_6  [C0603]  124.84 141.11 0 bottom
C95830  *22u/6.3V_6  [C0603]  116.4 154.42 180 bottom
C95831  820p/50V_4  [C0402]  121.41 142.22 0 bottom
C95832  1u/6.3V_2  [C0201]  114.07 151.48 270 bottom
C95833  1u/6.3V_2  [C0201]  129.67 151.27 90 bottom
C95834  220p/50V_4  [C0402]  130.17 114.6 180 top
C95837  0.22u/6.3V_2  [C0201]  60.85 39.34 90 top
C95838  0.22u/6.3V_2  [C0201]  70 47.9 90 top
C95839  0.22u/6.3V_2  [C0201]  68.47 47.9 90 top
C95840  0.22u/6.3V_2  [C0201]  69.24 47.9 90 top
C95841  0.22u/6.3V_2  [C0201]  70.76 47.9 90 top
C95842  0.22u/6.3V_2  [C0201]  77.49 47.08 0 top
C95843  0.22u/6.3V_2  [C0201]  72.54 47.84 90 top
C95844  0.22u/6.3V_2  [C0201]  73.3 47.84 90 top
C95845  0.22u/6.3V_2  [C0201]  77.49 46.32 0 top
C95846  0.22u/6.3V_2  [C0201]  44.85 42 90 top
C95847  0.22u/6.3V_2  [C0201]  43.33 42 90 top
C95848  0.22u/6.3V_2  [C0201]  44.09 42 90 top
C95849  0.22u/6.3V_2  [C0201]  45.61 42 90 top
C95850  0.22u/6.3V_2  [C0201]  54.63 50.89 90 top
C95851  0.22u/6.3V_2  [C0201]  53.11 50.89 90 top
C95852  0.22u/6.3V_2  [C0201]  53.87 50.89 90 top
C95853  0.22u/6.3V_2  [C0201]  55.39 50.89 90 top
C95854  0.22u/6.3V_2  [C0201]  61.03 48.94 0 top
C95855  0.22u/6.3V_2  [C0201]  57.25 50.89 90 top
C95856  0.22u/6.3V_2  [C0201]  58.01 50.89 90 top
C95857  0.22u/6.3V_2  [C0201]  61.03 48.18 0 top
C95858  0.1u/10V_2  [C0201]  42.57 35.78 180 bottom
C95859  0.1u/10V_2  [C0201]  46.27 33.47 180 bottom
C95860  0.22u/6.3V_2  [C0201]  50.97 40.91 0 top
C95861  0.1u/10V_2  [C0201]  52.27 44.67 180 bottom
C95862  10u/6.3V_4  [C0402_2]  51.61 49.34 180 bottom
C95863  1u/6.3V_2  [C0201]  48.86 38.27 0 bottom
C95864  1u/6.3V_2  [C0201]  52.22 48.23 90 bottom
C95865  10u/6.3V_4  [C0402_2]  50.34 32.53 270 bottom
C95866  0.22u/6.3V_2  [C0201]  47.47 42 90 top
C95867  1u/6.3V_2  [C0201]  49.27 32.66 90 bottom
C95868  1u/6.3V_2  [C0201]  58.64 47.13 0 bottom
C95869  0.1u/10V_2  [C0201]  55.57 42.89 180 bottom
C95870  0.22u/6.3V_2  [C0201]  48.23 42 90 top
C95871  0.22u/6.3V_2  [C0201]  50.97 40.15 0 top
C95873  0.22u/6.3V_2  [C0201]  60.09 39.34 90 top
C95874  0.22u/6.3V_2  [C0201]  58.57 39.34 90 top
C95875  0.22u/6.3V_2  [C0201]  59.33 39.34 90 top
C95876  0.22u/6.3V_2  [C0201]  285.29 65.93 0 top
C95877  0.22u/6.3V_2  [C0201]  285.29 65.17 0 top
C95878  0.22u/6.3V_2  [C0201]  287.04 66.51 270 top
C95879  0.22u/6.3V_2  [C0201]  287.8 66.51 270 top
C95880  WIGIG@0.1u/10V_2  [C0201]  50.19 66.77 0 top
C95881  WIGIG@0.1u/10V_2  [C0201]  50.19 65.88 0 top
C95882  WIGIG@0.1u/10V_2  [C0201]  50.19 68.55 0 top
C95883  WIGIG@0.1u/10V_2  [C0201]  50.19 67.66 0 top
C95884  WIGIG@0.1u/10V_2  [C0201]  56.79 68.34 0 bottom
C95886  WIGIG@0.1u/10V_2  [C0201]  56.66 69.89 0 bottom
C95887  WIGIG@0.1u/10V_2  [C0201]  56.66 70.63 0 bottom
C95888  WIGIG@0.1u/10V_2  [C0201]  48.33 70.48 0 top
C95889  WIGIG@0.1u/10V_2  [C0201]  48.33 69.51 0 top
C95892  1u/6.3V_2  [C0201]  342.29 49.37 270 top
C95893  47u/6.3V_6  [C0603]  341.14 47.34 90 top
C95894  47u/6.3V_6  [C0603]  341.14 50 270 top
C95895  0.01u/50V_4  [C0402]  30.5 54.45 270 bottom
C95896  0.01u/50V_4  [C0402]  32.41 50.26 180 top
C95897  WIGIG@0.22u/6.3V_2  [C0201]  285.26 58.21 180 top
C95898  WIGIG@0.22u/6.3V_2  [C0201]  285.26 58.97 180 top
C95899  180p/50V_4  [C0402]  352.06 81.25 270 bottom
C95902  10u/6.3V_4  [C0402_2]  36.47 32.1 270 top
C95903  0.1u/10V_2  [C0201]  35.76 30.85 180 top
C95904  10u/6.3V_4  [C0402_2]  30.45 32.71 180 bottom
C95905  0.1u/10V_2  [C0201]  31.31 33.72 180 bottom
C95907  *0.1u/10V_2  [C0201]  327.68 75.66 270 top
C95908  WIGIG@0.1u/10V_2  [C0201]  56.79 69.1 0 bottom
C95909  *47u/6.3V_6  [C0603]  224.94 134.54 0 top
C95911  10u/6.3V_4  [C0402_2]  215.39 76.94 270 bottom
C95912  10u/6.3V_4  [C0402_2]  263.32 57.7 0 bottom
C95913  10u/6.3V_4  [C0402_2]  239.57 75.4 90 bottom
C95914  10u/6.3V_4  [C0402_2]  269.84 76.57 90 bottom
C95915  22u/6.3V_6  [C0603]  182.77 115.79 270 top
C95919  22u/6.3V_6  [C0603]  184.3 115.79 270 top
C95922  47u/6.3V_6  [C0603]  189.89 111.6 270 top
C95924  47u/6.3V_6  [C0603]  187.85 112.61 270 top
C95928  *47u/6.3V_6  [C0603]  114.83 118.84 0 top
C95929  *47u/6.3V_6  [C0603]  114.83 120.87 0 top
C95930  *47u/6.3V_6  [C0603]  114.83 116.81 0 top
C95933  220p/50V_4  [C0402]  257.96 171.92 180 bottom
C95934  *220p/50V_4  [C0402]  56.84 75.66 90 bottom
C95935  *220p/50V_4  [C0402]  53.06 76.83 90 bottom
C95939  *47u/6.3V_8  [C0805]  64.57 26.69 90 top
C95940  *47u/6.3V_8  [C0805]  66.58 26.69 90 top
C95941  *47u/6.3V_8  [C0805]  62.57 26.74 90 top
C95942  *47u/6.3V_8  [C0805]  46.93 22.98 90 top
C95943  *47u/6.3V_8  [C0805]  39.8 26 0 top
C95944  *47u/6.3V_8  [C0805]  44.76 27.7 90 top
C95946  M_PB@180p/50V_4  [C0402]  376.65 12.95 90 bottom
C95962  4.7u/6.3V_4  [C0402_2]  17.19 24.93 0 top
C95973  1u/6.3V_2  [C0201]  14.52 27.17 0 top
C95974  1u/6.3V_2  [C0201]  20.06 29.99 270 top
C95975  1u/10V_4_X7R  [C0402]  21 26.71 90 top
C95976  0.1u/16V_4_X7R  [C0402]  19.6 28.87 90 bottom
C95977  2.2u/10V_4  [C0402]  18.99 31.82 270 bottom
C95978  2.2u/10V_6_X7R  [C0603]  22.22 21.07 0 top
C95979  2.2u/10V_6_X7R  [C0603]  16.28 17.75 90 bottom
C95980  0.1u/10V_2  [C0201]  16.15 18.25 90 top
C95981  10u/6.3V_4  [C0402_2]  14.96 17.75 90 bottom
C95982  1u/10V_4_X7R  [C0402]  19.81 21.28 180 top
C95983  2.2u/10V_4  [C0402]  18.51 12.95 270 top
C95984  1u/10V_4_X7R  [C0402]  18.79 16.76 90 bottom
C95985  1u/10V_4_X7R  [C0402]  19.76 16.76 90 bottom
C95986  2.2u/10V_4  [C0402]  19.58 12.79 270 top
C95987  CLK@1u/6.3V_2  [C0201]  45.11 54.83 0 top
C95988  CLK@1u/6.3V_2  [C0201]  44.65 61.69 90 top
C95989  CLK@0.1u/10V_2  [C0201]  43.86 61.69 270 top
C95990  CLK@22u/6.3V_6  [C0603]  45.89 63.95 270 top
C95991  CLK@1u/6.3V_2  [C0201]  33.68 57.04 270 top
C95992  CLK@0.1u/10V_2  [C0201]  34.56 57.04 90 top
C95993  1u/6.3V_2  [C0201]  350.41 52.04 270 bottom
C95994  1u/6.3V_2  [C0201]  357.65 58.64 270 top
C95998  1u/6.3V_2  [C0201]  331.87 48.99 90 top
C96009  0.22u/6.3V_2  [C0201]  370.73 26.38 270 bottom
C96010  2.2u/10V_4  [C0402]  367.56 21.05 270 top
C96011  2.2u/10V_4  [C0402]  364.13 21.05 270 top
C96012  2.2u/10V_4  [C0402]  373.12 19.24 180 top
C96013  10u/6.3V_4  [C0402_2]  366.29 21.05 270 top
C96014  22u/6.3V_6  [C0603]  363.88 32.86 0 top
C96015  22u/6.3V_6  [C0603]  363.88 34.28 0 top
C96016  10u/6.3V_4  [C0402_2]  369.84 21.05 90 top
C96017  1u/6.3V_2  [C0201]  370.61 24.22 0 bottom
C96018  220p/50V_4  [C0402]  371.37 28.54 90 bottom
C96019  220p/50V_4  [C0402]  371.52 32.3 270 bottom
C96020  *Tobii@180p/50V_4  [C0402]  29.1 78.83 0 top
C96021  *Tobii@180p/50V_4  [C0402]  31.01 78.83 180 top
C96022  *Tobii@220p/50V_4  [C0402]  26.94 88.05 0 top
C96023  Tobii@1000p/50V_4  [C0402]  28.21 82.52 90 bottom
C96024  Tobii@0.1u/10V_2  [C0201]  28.82 81.58 180 top
C96026  22u/6.3V_6  [C0603]  366.54 32.86 180 top
C96027  22u/6.3V_6  [C0603]  366.54 34.28 180 top
C96028  *22u/6.3V_6  [C0603]  369.49 33.75 0 top
C96030  *22u/6.3V_6  [C0603]  372.13 33.49 180 top
C96031  0.1u/10V_2  [C0201]  269.26 126.81 180 top
C96033  0.1u/10V_2  [C0201]  300.6 78.35 90 top
C96034  0.1u/10V_2  [C0201]  299.46 66.49 180 bottom
C96035  0.1u/10V_2  [C0201]  303.17 59.3 270 bottom
C96036  0.1u/10V_2  [C0201]  304.24 59.88 270 bottom
C96038  4.7u/6.3V_4  [C0402_2]  23.74 22.39 0 top
C96039  4.7u/6.3V_4  [C0402_2]  23.57 24.58 0 top
C96042  10u/6.3V_4  [C0402_2]  114.32 146.52 270 bottom
C96043  1u/6.3V_2  [C0201]  176.98 174.21 270 bottom
C96045  1u/6.3V_2  [C0201]  133.5 176.75 270 bottom
C96046  1u/6.3V_2  [C0201]  126.39 142.59 180 bottom
C96047  1u/6.3V_2  [C0201]  115.46 130.27 90 bottom
C96049  1u/6.3V_2  [C0201]  119.78 129.63 180 bottom
C96051  1u/6.3V_2  [C0201]  123.36 125.95 270 bottom
C96052  1u/6.3V_2  [C0201]  121.56 125.44 270 bottom
C96053  10u/6.3V_4  [C0402_2]  115.21 132.3 90 bottom
C96054  1u/6.3V_2  [C0201]  122.83 132.43 90 bottom
C96057  10u/6.3V_4  [C0402_2]  115.08 127.35 270 bottom
C96058  10u/6.3V_4  [C0402_2]  169.57 168.75 90 bottom
C96059  1u/6.3V_2  [C0201]  118.89 122.9 0 bottom
C96060  1u/6.3V_2  [C0201]  120.67 122.9 180 bottom
C96061  10u/6.3V_4  [C0402_2]  169.57 164.81 270 bottom
C96062  1u/6.3V_2  [C0201]  119.53 149.8 90 bottom
C96063  1u/6.3V_2  [C0201]  127.02 148.81 0 bottom
C96064  1u/6.3V_2  [C0201]  116.35 149.95 90 bottom
C96065  1u/6.3V_2  [C0201]  117.5 149.19 90 bottom
C96066  1u/6.3V_2  [C0201]  119.91 147.54 0 bottom
C96067  1u/6.3V_2  [C0201]  122.83 151.35 90 bottom
C96068  1u/6.3V_2  [C0201]  123.34 144.87 270 bottom
C96069  10u/6.3V_4  [C0402_2]  202.2 112.11 0 top
C96070  1u/6.3V_2  [C0201]  121.43 145.3 270 bottom
C96071  10u/6.3V_4  [C0402_2]  203.98 112.11 0 top
C96072  10u/6.3V_4  [C0402_2]  196.87 145 0 bottom
C96073  1u/6.3V_2  [C0201]  121.43 151.1 90 bottom
C96074  1u/6.3V_2  [C0201]  138.2 169 270 bottom
C96075  10u/6.3V_4  [C0402_2]  194.97 145 0 bottom
C96076  1u/6.3V_2  [C0201]  135.91 171.92 0 bottom
C96077  1u/6.3V_2  [C0201]  134.26 167.1 270 bottom
C96078  1u/6.3V_2  [C0201]  129.31 169.89 0 bottom
C96079  1u/6.3V_2  [C0201]  133.37 169.89 270 bottom
C96080  1u/6.3V_2  [C0201]  130.07 171.92 180 bottom
C96081  1u/6.3V_2  [C0201]  132.23 174.21 270 bottom
C96082  1u/6.3V_2  [C0201]  133.5 174.21 270 bottom
C96083  10u/6.3V_4  [C0402_2]  193.06 145 0 bottom
C96084  1u/6.3V_2  [C0201]  198.9 157.7 90 bottom
C96085  10u/6.3V_4  [C0402_2]  208.05 137.25 270 bottom
C96086  10u/6.3V_4  [C0402_2]  208.05 135.09 270 bottom
C96087  1u/6.3V_2  [C0201]  199.66 153 180 bottom
C96088  1u/6.3V_2  [C0201]  203.22 154.4 180 bottom
C96089  10u/6.3V_4  [C0402_2]  157.37 166.84 90 bottom
C96090  1u/6.3V_2  [C0201]  126.13 168.49 90 bottom
C96091  1u/6.3V_2  [C0201]  153.31 171.8 90 bottom
C96092  1u/6.3V_2  [C0201]  147.85 170.02 180 bottom
C96093  1u/6.3V_2  [C0201]  149.88 168.75 90 bottom
C96094  1u/6.3V_2  [C0201]  154.58 170.53 0 bottom
C96095  1u/6.3V_2  [C0201]  154.96 171.8 180 bottom
C96096  1u/6.3V_2  [C0201]  150.64 171.67 90 bottom
C96097  10u/6.3V_4  [C0402_2]  197.88 132.22 0 bottom
C96098  1u/6.3V_2  [C0201]  148.69 171.87 0 bottom
C96099  10u/6.3V_4  [C0402_2]  192.54 132.01 0 bottom
C96100  10u/6.3V_4  [C0402_2]  207.79 125.31 270 bottom
C96101  1u/6.3V_2  [C0201]  151.4 172.43 270 bottom
C96102  1u/6.3V_2  [C0201]  151.79 176.88 270 bottom
C96103  10u/6.3V_4  [C0402_2]  207.79 123.41 270 bottom
C96104  1u/6.3V_2  [C0201]  173.25 170.02 180 bottom
C96105  1u/6.3V_2  [C0201]  174.52 164.05 180 bottom
C96106  1u/6.3V_2  [C0201]  201.32 155.54 0 bottom
C96107  1u/6.3V_2  [C0201]  135.91 174.59 180 bottom
C96108  1u/6.3V_2  [C0201]  179.09 171.92 0 bottom
C96109  1u/6.3V_2  [C0201]  172.23 171.92 0 bottom
C96110  1u/6.3V_2  [C0201]  173.5 171.92 180 bottom
C96111  10u/6.3V_4  [C0402_2]  183.28 167.48 270 bottom
C96112  1u/6.3V_2  [C0201]  176.04 172.56 270 bottom
C96113  10u/6.3V_4  [C0402_2]  175.03 179.29 180 bottom
C96114  10u/6.3V_4  [C0402_2]  114.45 144.11 270 bottom
C96115  1u/6.3V_2  [C0201]  176.93 175.48 270 bottom
C96116  1u/6.3V_2  [C0201]  116.61 147.41 0 bottom
C96117  10u/6.3V_4  [C0402_2]  114.45 142.08 90 bottom
C96118  1u/6.3V_2  [C0201]  118.64 129.63 180 bottom
C96119  1u/6.3V_2  [C0201]  116.86 128.49 180 bottom
C96120  1u/6.3V_2  [C0201]  150.57 177 270 bottom
C96121  1u/6.3V_2  [C0201]  206.01 148.68 0 bottom
C96122  1u/6.3V_2  [C0201]  204.87 148.68 0 bottom
C96123  1u/6.3V_2  [C0201]  203.47 148.68 0 bottom
C96124  1u/6.3V_2  [C0201]  201.95 148.68 0 bottom
C96125  10u/6.3V_4  [C0402_2]  126.26 176.11 270 bottom
C96126  1u/6.3V_2  [C0201]  205.89 139.41 180 bottom
C96127  10u/6.3V_4  [C0402_2]  131.21 178.91 180 bottom
C96128  10u/6.3V_4  [C0402_2]  127.15 135.86 180 bottom
C96129  1u/6.3V_2  [C0201]  205.76 154.4 180 bottom
C96130  1u/6.3V_2  [C0201]  200.93 157.52 270 bottom
C96131  10u/6.3V_4  [C0402_2]  139.85 167.61 270 bottom
C96132  1u/6.3V_2  [C0201]  199.54 151.48 270 bottom
C96133  1u/6.3V_2  [C0201]  193.95 154.27 180 bottom
C96134  1u/6.3V_2  [C0201]  202.2 140.81 270 bottom
C96135  1u/6.3V_2  [C0201]  200.93 142.13 270 bottom
C96136  1u/6.3V_2  [C0201]  199.66 135.47 270 bottom
C96137  1u/6.3V_2  [C0201]  198.94 141.82 180 bottom
C96138  1u/6.3V_2  [C0201]  200.83 117.26 90 bottom
C96139  10u/6.3V_4  [C0402_2]  149.37 179.04 180 bottom
C96140  1u/6.3V_2  [C0201]  199.54 115.92 90 bottom
C96141  10u/6.3V_4  [C0402_2]  157.5 177.64 270 bottom
C96142  10u/6.3V_4  [C0402_2]  157.5 175.73 270 bottom
C96143  1u/6.3V_2  [C0201]  200.93 116.04 90 bottom
C96144  1u/6.3V_2  [C0201]  200.89 122.13 0 bottom
C96145  10u/6.3V_4  [C0402_2]  143.4 176.11 270 top
C96146  1u/6.3V_2  [C0201]  198.9 122.77 90 bottom
C96147  1u/6.3V_2  [C0201]  200.81 135.98 270 bottom
C96148  1u/6.3V_2  [C0201]  203.47 135.98 270 bottom
C96149  1u/6.3V_2  [C0201]  203.6 140.81 90 bottom
C96150  1u/6.3V_2  [C0201]  205 138.4 0 bottom
C96151  1u/6.3V_2  [C0201]  199.03 117.31 180 bottom
C96152  1u/6.3V_2  [C0201]  193.82 119.22 180 bottom
C96153  10u/6.3V_4  [C0402_2]  143.4 173.47 270 top
C96154  1u/6.3V_2  [C0201]  175.71 175.68 270 bottom
C96155  10u/6.3V_4  [C0402_2]  207.67 156.56 90 bottom
C96156  10u/6.3V_4  [C0402_2]  207.79 154.02 270 bottom
C96157  1u/6.3V_2  [C0201]  205.76 155.54 180 bottom
C96158  1u/6.3V_2  [C0201]  205.89 120.49 180 bottom
C96159  0.1u/10V_2  [C0201]  272.84 130.52 180 top
C96160  10u/6.3V_4  [C0402_2]  208 65.73 0 bottom
C96161  1u/6.3V_2  [C0201]  202.84 72.86 270 top
C96162  10u/6.3V_4  [C0402_2]  203.6 74.13 0 top
C96163  10u/6.3V_4  [C0402_2]  207.97 64.53 0 bottom
C96164  1u/6.3V_2  [C0201]  202.08 72.86 270 top
C96165  10u/6.3V_4  [C0402_2]  203.6 75.4 0 top
C96166  *47u/6.3V_6  [C0603]  296.18 50.74 0 bottom
C96167  *47u/6.3V_6  [C0603]  287.07 75.53 0 top
C96168  *47u/6.3V_6  [C0603]  290.47 77.87 180 top
C96201  2.2u/10V_4  [C0402]  62.76 38.45 0 bottom
C96202  2.2u/10V_4  [C0402]  70.89 46.32 180 bottom
C96203  2.2u/10V_4  [C0402]  47.77 41.11 0 bottom
C96204  2.2u/10V_4  [C0402]  55.27 50.38 180 bottom
C96207  M_KB@0.1u/10V_2  [C0201]  129.05 60.29 90 bottom
C96209  330u/2V_7343H1.9  [CC7343]  185.57 92.93 270 top
C96210  4.7u/6.3V_4  [C0402_2]  206.7 116.17 90 bottom
C96211  4.7u/6.3V_4  [C0402_2]  208.5 140.94 90 bottom
C96212  4.7u/6.3V_4  [C0402_2]  207.31 151.15 180 bottom
C96213  4.7u/6.3V_4  [C0402_2]  172.05 179.34 90 bottom
C96214  4.7u/6.3V_4  [C0402_2]  153.26 178.81 0 bottom
C96215  4.7u/6.3V_4  [C0402_2]  128.29 177.92 0 bottom
C96216  4.7u/6.3V_4  [C0402_2]  115.06 151.98 270 bottom
C96217  4.7u/6.3V_4  [C0402_2]  114.37 125.37 90 bottom
C96218  180p/50V_4  [C0402]  186.81 64.3 270 bottom
C96219  180p/50V_4  [C0402]  189.96 60.62 90 bottom
C96220  0.1u/10V_2  [C0201]  178.4 59.63 0 bottom
C96221  *0.1u/10V_2  [C0201]  195.35 53.46 270 bottom
C96222  2.2u/10V_4  [C0402]  16.35 28.24 90 bottom
C96223  *0.1u/10V_2  [C0201]  20.98 13.35 180 bottom
C96224  *50p/25V_2  [C0201]  19.3 13.89 180 bottom
C96225  SUB@2.2u/10V_4  [C0402]  35.66 36.11 0 top
C96226  SUB@2.2u/10V_4  [C0402]  38.42 44.7 0 top
C96227  SUB@0.1u/10V_2  [C0201]  42.77 42.1 0 bottom
C96228  SUB@10u/6.3V_4  [C0402_2]  41.09 44.06 90 bottom
C96229  SUB@0.1u/10V_2  [C0201]  40.71 40.33 270 bottom
C96230  SUB@10u/6.3V_4  [C0402_2]  42.39 44.06 90 bottom
C96231  SUB@0.1u/10V_2  [C0201]  29.99 44.11 270 top
C96232  SUB@1u/6.3V_2  [C0201]  26.26 38.4 0 top
C96233  SUB@0.1u/10V_2  [C0201]  26.03 40.73 0 top
C96234  SUB@2.2u/10V_4  [C0402]  25.95 39.31 0 top
C96235  SUB@0.1u/10V_2  [C0201]  29.28 42.28 270 bottom
C96236  SUB@10u/6.3V_4  [C0402_2]  28.29 42.23 90 bottom
C96237  SUB@0.1u/10V_2  [C0201]  32.58 43.83 90 bottom
C96240  HDD@0.1u/10V_2  [C0201]  69.84 24.76 0 bottom
C96241  HDD@0.1u/10V_2  [C0201]  69.84 23.99 0 bottom
C96242  *HDD@47u/6.3V_8  [C0805]  68.55 32.33 180 top
C96243  SUB@33p/50V_4  [C0402]  39.24 47.87 270 bottom
C96244  SUB@33p/50V_4  [C0402]  38.2 47.87 270 bottom
C96245  SUB@33p/50V_4  [C0402]  36.11 47.87 270 bottom
C96246  SUB@33p/50V_4  [C0402]  37.15 47.87 270 bottom
C96247  0.1u/10V_2  [C0201]  303.17 75.63 270 bottom
C96248  0.1u/10V_2  [C0201]  299 75 0 bottom
C96249  0.1u/10V_2  [C0201]  305.53 54.25 180 bottom
C96250  1000p/50V_4  [C0402]  375.64 12.44 90 bottom
C96251  1000p/50V_4  [C0402]  374.26 12.06 180 bottom
C96252  0.1u/10V_2  [C0201]  377.44 8.3 270 bottom
C96253  0.1u/10V_2  [C0201]  367.13 36.69 90 bottom
C96254  *0.1u/10V_2  [C0201]  377.34 7.2 90 bottom
C96255  *0.1u/10V_2  [C0201]  365.48 41.6 270 bottom
C96256  0.1u/10V_2  [C0201]  379.88 10.25 180 bottom
C96257  10u/6.3V_4  [C0402_2]  379.75 8.55 180 bottom
C96258  0.1u/10V_2  [C0201]  379.5 12.16 180 bottom
C96259  10u/6.3V_4  [C0402_2]  377.74 12.79 270 bottom
C96260  0.1u/10V_2  [C0201]  368.96 38.24 270 bottom
C96261  M_KB@22u/6.3V_4  [C0402_2]  130.7 59.4 180 bottom
C96263  22u/6.3V_6  [C0603]  367.47 53.62 180 top
C96264  330u/2.5V_3528H1.9  [C3528]  177.44 100.8 270 top
C96265  330u/2.5V_3528H1.9  [C3528]  175.41 87.09 180 top
C96266  330u/2.5V_3528H1.9  [C3528]  189.86 93.11 90 top
C96267  M_KB@0.1u/10V_2  [C0201]  121.43 58.39 0 bottom
C96268  M_KB@22u/6.3V_4  [C0402_2]  130.7 58.13 0 bottom
C96269  M_KB@1000p/50V_4  [C0402]  127.4 59.53 0 bottom
C96270  *1000p/50V_4  [C0402]  127.4 60.54 0 bottom
C96273  *M_KB@0.1u/10V_2  [C0201]  121.43 59.22 0 bottom
C96279  M_KB@0.1u/10V_2  [C0201]  121.43 60.04 180 bottom
C96280  100p/50V_4  [C0402]  359.56 79.21 180 bottom
C96281  0.1u/25V_2  [C0201]  359.56 78.32 180 bottom
CLIP1  FBFG200601  [CLIP-39X39-89X20-3P]  125 109 0 top
CLIP2  FBFG200601  [CLIP-39X39-89X20-3P]  112 116 90 top
CLIP3  FBFG200601  [CLIP-39X39-89X20-3P]  112 149.1 90 top
CLIP4  FBFG200601  [CLIP-39X39-89X20-3P]  209.5 116.4 90 top
CLIP5  FBFG200601  [CLIP-39X39-89X20-3P]  131.5 181.4 0 top
CLIP6  FBFG200601  [CLIP-39X39-89X20-3P]  179.5 181.4 0 top
CLIP7  FBFG200601  [CLIP-39X39-89X20-3P]  209.5 156 90 top
CLIP8  FBFG200601  [CLIP-39X39-89X20-3P]  196.5 109 0 top
CN11  HDD@MAIN_SATA_CONN  [GS12201-1011-9F-20P-L-SMT]  73.95 30.9 90 top
CN18  DX07S024JJ2  [UB31-DX07S024JJ2-24P-TBT]  382.6 43.5 90 top
CN2039  SUB@50281-00401-001_Header  [50281-00401-001-4P-L]  85.8 46.89 0 top
CN2042  GS12401-1011P-7H  [GS12401-1011-9H-40P-R]  349.1 83 180 top
CN2043  3VD11201-D7AC-7H  [DP-3VD11201-D7AC-7H-20P-SMT]  247.5 178.8 180 top
CN2044  2HE1673-001111F  [HDMI-2HE1673-021111F-19P]  224.5 179.63 180 top
CN2045  50273-0040N-V09  [50273-0040N-V09-4P-L]  325.88 82.9 180 top
CN2046  50273-0040N-V09  [50273-0040N-V09-4P-L]  55.6 81.1 180 top
CN2048  P_KB@50584-02601-001  [50591-02601-V01-26P-L]  216.99 47.59 0 top
CN2049  M_KB@50278-006T1-001  [50278-006T1-001-6P-L]  122.62 56 270 top
CN2054  53014-00201-V09  [ML1220-SMT]  41.5 83.51 0 top
CN2058  2SJ3072-170111F  [PHJK-2SJ3072-170111F-6P]  6 11 270 top
CN2059  2SJ3072-170111F  [PHJK-2SJ3072-170111F-6P]  6 25 270 top
CN2060  50281-00401-001_Header  [50281-00401-001-4P-L]  21.8 5.23 0 top
CN2061  130456-481  [RJ45-C100KB-10809-L-8P]  381.37 78.19 90 top
CN2062  ADDR0107-P005A  [DDR4-ADDR0107-P005A-RVS-SMT]  244.81 70.68 0 top
CN2063  D4AR0-26001-1P80  [DDR4-D4AR0-26001-1P80-RVS-SMT]  244.81 57.68 0 top
CN2064  TAR24-9V1391  [UB3-TAR24-9V1391-9P]  5.3 41 270 top
CN2065  TAR24-9V1391  [UB3-TAR24-9V1391-9P]  5.3 59 270 top
CN2066  UARE9-4K1921  [UB2-UARE9-4K1921-4P-L]  12.49 78 270 top
CN2067  TAR24-9V1391  [UB3-TAR24-9V1391-9P]  381.7 60.5 90 top
CN2068  NGFF_AKEY  [NGFF-NASA0-S6701-TS48-75P-KA]  55.18 65 270 top
CN2069  NASM0-B6701-TS18  [NGFF-NASM0-B6701-TS18-75P-KM]  65.99 18.19 0 top
CN2070  NASM0-B6701-TS18  [NGFF-NASM0-B6701-TS18-75P-KM]  39.99 18.19 0 top
CN2071  P_PB@51619-0080N-001  [51619-0080N-001-8P-L]  187.1 46.35 0 top
CN2074  LOGO@50273-0060N-V09  [50273-0060N-V09-6P-L]  35.3 93.8 180 top
CN2075  P_KB@196332-14041-3  [51619-0140N-001-14P-L]  251.24 46.45 0 top
CN2076  M_TP@51619-0200N-V03  [51619-0200N-V03-20P-L]  137.3 58.45 0 top
CN2077  51653-0040N-V01  [51653-0040N-V01-4P-L]  81.7 77.8 270 top
